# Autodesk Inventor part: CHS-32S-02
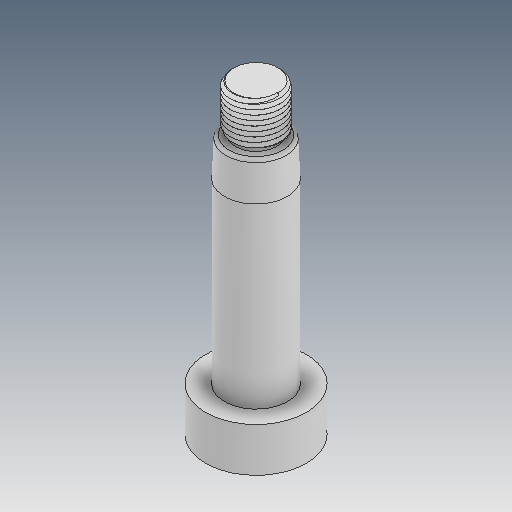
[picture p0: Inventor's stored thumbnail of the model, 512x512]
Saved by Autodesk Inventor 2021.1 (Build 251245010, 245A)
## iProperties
Created: 2021-05
Part Number: CHS-32S-02
Material: Ogólny
Document SubType Name: Modeling
Designer: user
Density: 1 g/cm^3
Appearance: Domyślna
Author: user
Revision Number: ÈÎºÎ
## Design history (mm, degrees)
feature "ÊäÈë1"
feature "ÊäÈë2"
node "Bryła1"
node "Bryła2"
